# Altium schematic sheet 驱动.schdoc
size 594 x 419 mm; Symbol: Drawing-Symbol_A4; Company: 嘉立创EDA; Version: V1.0; Page Size: A4; @Project Name: FOC; @Update Date: 2026-07-20; @Create Date: 2026-07-20; Device: Drawing-Symbol_A4; @Board Name: Board1; @Page Name: P1; @Create Time: 00:30:19; @Page Count: 2; @Page No: 2; @Schematic Name: Schematic1; @Update Time: 00:30:19; @Assembly Variant: Basic; Border: 1; Title Block Position: 3; Size: A4; Width: 2338; Height: 1652; Region Start: 1; X Region Count: 6; Y Region Count: 4; Blade Width: 10
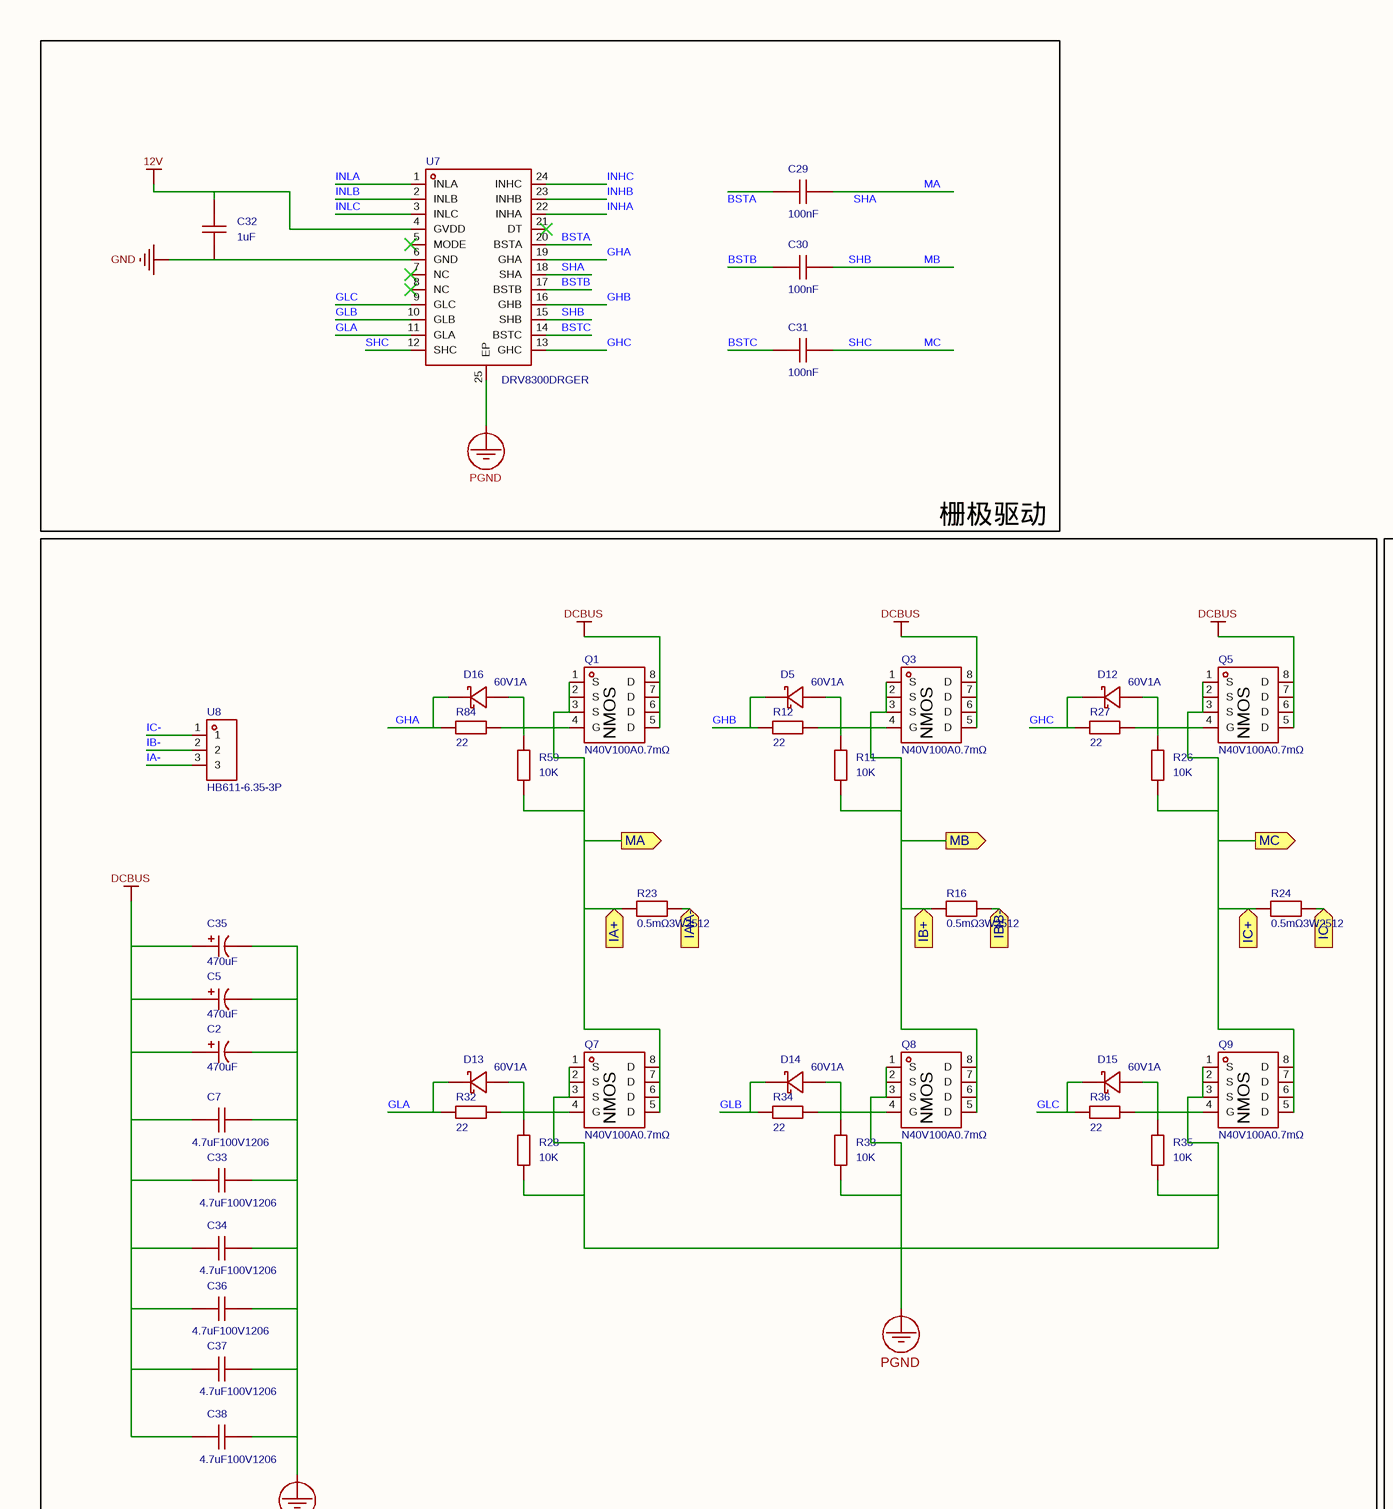
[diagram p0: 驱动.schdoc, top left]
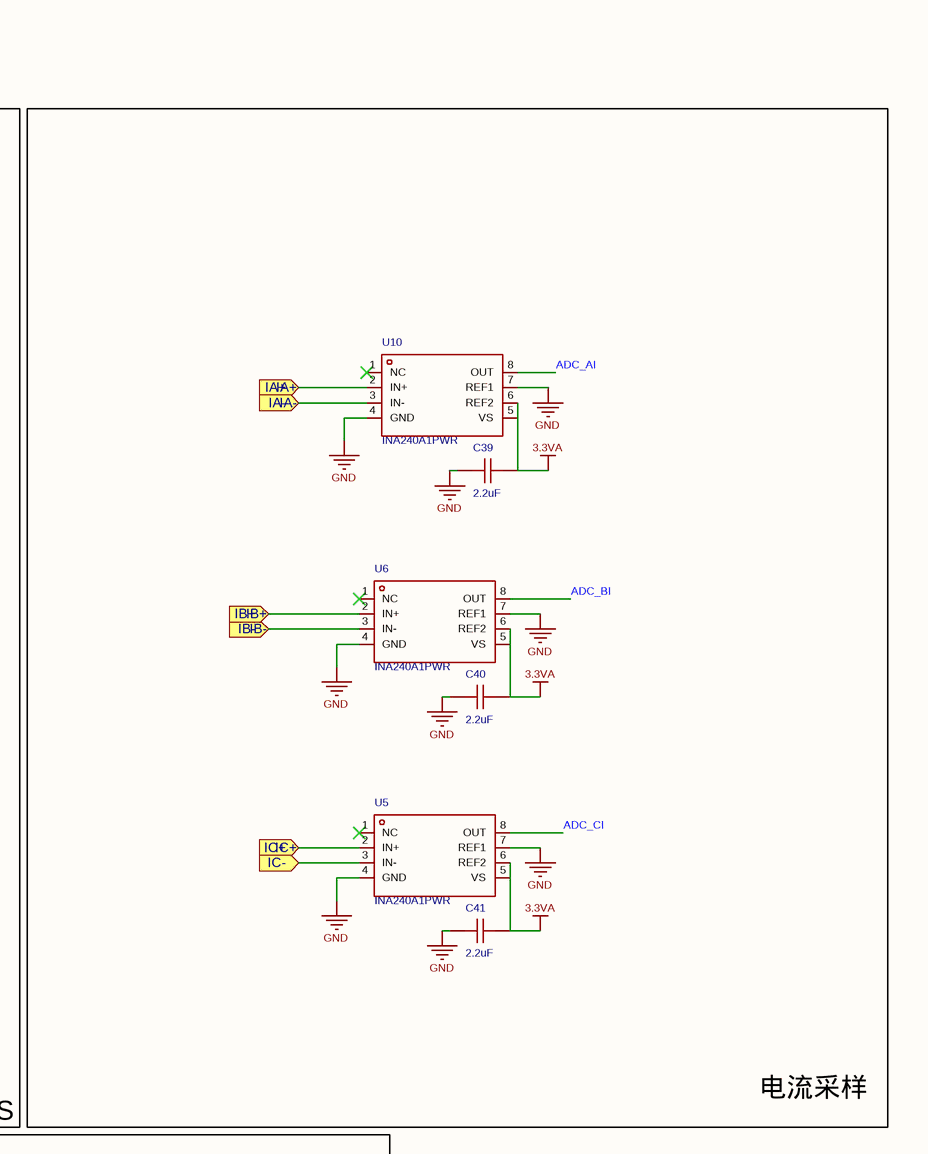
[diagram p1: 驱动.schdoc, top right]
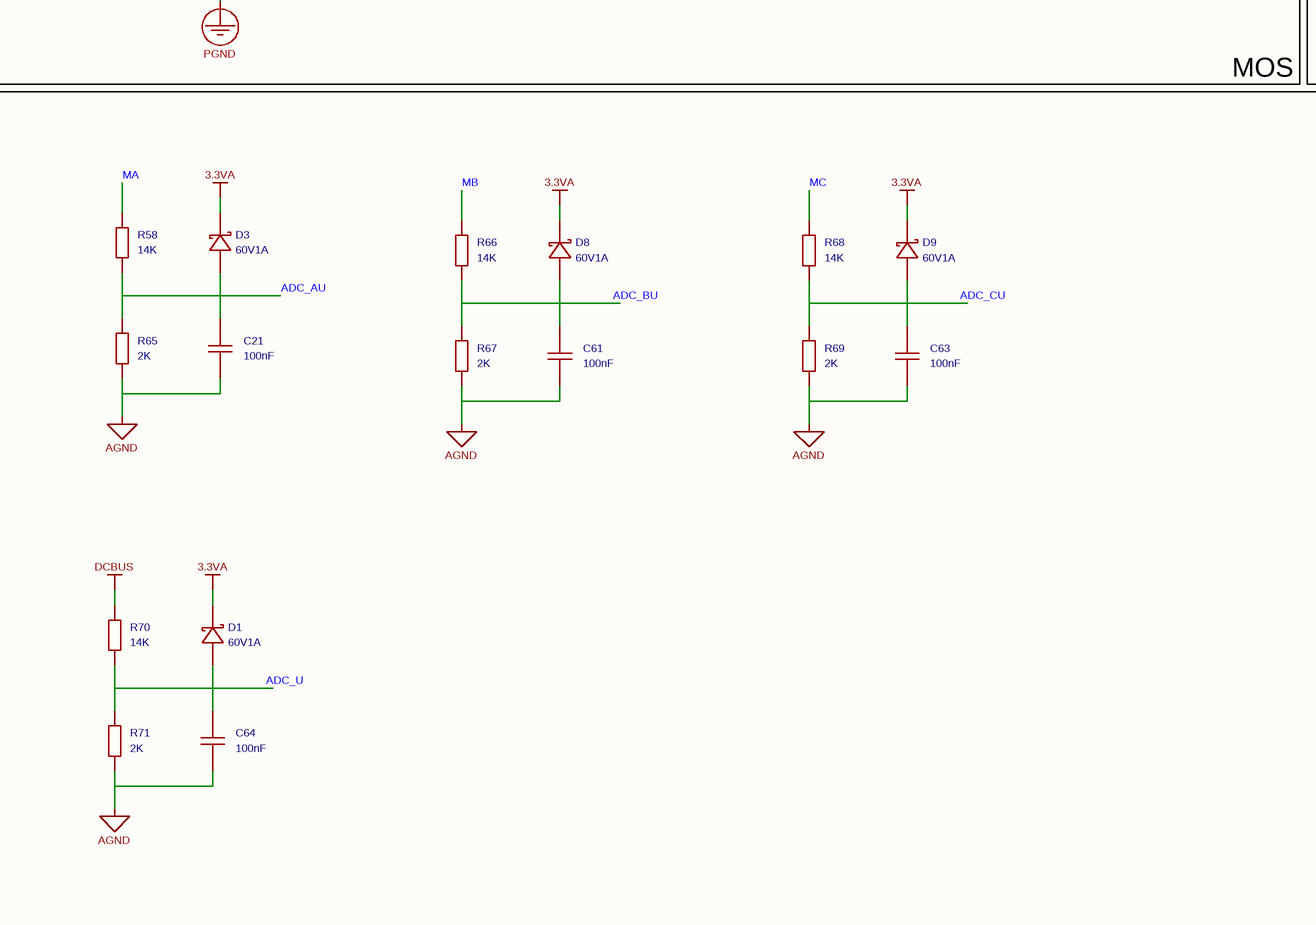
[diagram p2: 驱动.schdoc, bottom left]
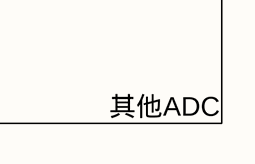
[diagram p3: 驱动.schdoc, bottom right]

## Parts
C2  470uF  [CAP-TH_BD13.0-P5.00-D0.6-FD]
C5  470uF  [CAP-TH_BD13.0-P5.00-D0.6-FD]
C7  4.7uF100V1206  [C1206]
C21  100nF  [C0603]
C29  100nF  [C0603]
C30  100nF  [C0603]
C31  100nF  [C0603]
C32  1uF  [C0603]
C33  4.7uF100V1206  [C1206]
C34  4.7uF100V1206  [C1206]
C35  470uF  [CAP-TH_BD13.0-P5.00-D0.6-FD]
C36  4.7uF100V1206  [C1206]
C37  4.7uF100V1206  [C1206]
C38  4.7uF100V1206  [C1206]
C39  2.2uF  [C0603]
C40  2.2uF  [C0603]
C41  2.2uF  [C0603]
C61  100nF  [C0603]
C63  100nF  [C0603]
C64  100nF  [C0603]
D1  60V1A  [SOD-323_L1.7-W1.3-LS2.5-FD]
D3  60V1A  [SOD-323_L1.7-W1.3-LS2.5-FD]
D5  60V1A  [SOD-323_L1.7-W1.3-LS2.5-FD]
D8  60V1A  [SOD-323_L1.7-W1.3-LS2.5-FD]
D9  60V1A  [SOD-323_L1.7-W1.3-LS2.5-FD]
D12  60V1A  [SOD-323_L1.7-W1.3-LS2.5-FD]
D13  60V1A  [SOD-323_L1.7-W1.3-LS2.5-FD]
D14  60V1A  [SOD-323_L1.7-W1.3-LS2.5-FD]
D15  60V1A  [SOD-323_L1.7-W1.3-LS2.5-FD]
D16  60V1A  [SOD-323_L1.7-W1.3-LS2.5-FD]
Q1  N40V100A0.7mΩ  [PG-TDSON-8-FL_L5.0-W6.0-P1.27-LS6.2-BL]
Q3  N40V100A0.7mΩ  [PG-TDSON-8-FL_L5.0-W6.0-P1.27-LS6.2-BL]
Q5  N40V100A0.7mΩ  [PG-TDSON-8-FL_L5.0-W6.0-P1.27-LS6.2-BL]
Q7  N40V100A0.7mΩ  [PG-TDSON-8-FL_L5.0-W6.0-P1.27-LS6.2-BL]
Q8  N40V100A0.7mΩ  [PG-TDSON-8-FL_L5.0-W6.0-P1.27-LS6.2-BL]
Q9  N40V100A0.7mΩ  [PG-TDSON-8-FL_L5.0-W6.0-P1.27-LS6.2-BL]
R11  10K  [R0603]
R12  22  [R0603]
R16  0.5mΩ3W2512  [R2512]
R23  0.5mΩ3W2512  [R2512]
R24  0.5mΩ3W2512  [R2512]
R26  10K  [R0603]
R27  22  [R0603]
R28  10K  [R0603]
R32  22  [R0603]
R33  10K  [R0603]
R34  22  [R0603]
R35  10K  [R0603]
R36  22  [R0603]
R58  14K  [R0603]
R59  10K  [R0603]
R65  2K  [R0603]
R66  14K  [R0603]
R67  2K  [R0603]
R68  14K  [R0603]
R69  2K  [R0603]
R70  14K  [R0603]
R71  2K  [R0603]
R84  22  [R0603]
U5  INA240A1PWR  [TSSOP-8_L4.4-W3.0-P0.65-LS6.4-BL]
U6  INA240A1PWR  [TSSOP-8_L4.4-W3.0-P0.65-LS6.4-BL]
U7  DRV8300DRGER  [VQFN-24_L4.0-W4.0-P0.50-TL-EP2.5]
U8  HB611-6.35-3P  [CONN-TH_HB611-6.35-3P]
U10  INA240A1PWR  [TSSOP-8_L4.4-W3.0-P0.65-LS6.4-BL]

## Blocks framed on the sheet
栅极驱动: C29-C32 U7
MOS: C2 C5 C7 C33-C38 D5 D12-D16 Q1 Q3 Q5 Q7-Q9 R11 R12 R16 R23 R24 R26-R28 R32-R36 R59 R84 U8
电流采样: C39-C41 U5 U6 U10
其他ADC: C21 C61 C63 C64 D1 D3 D8 D9 R58 R65-R71

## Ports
IA+ (in), IA- (in), IB+ (in), IB- (in), IC+ (in), IC- (in), MA (out), MB (out), MC (out)

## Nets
3.3VA: C39.2 C40.2 C41.2 D1.2(K) D3.2(K) D8.2(K) D9.2(K) U5.5(VS) U5.6(REF2) U6.5(VS) U6.6(REF2) U10.5(VS) U10.6(REF2)
12V: C32.2 U7.4(GVDD)
AGND: C21.1 C61.1 C63.1 C64.1 R65.1 R67.1 R69.1 R71.1
DCBUS: C2.1 C5.1 C7.1 C33.1 C34.1 C35.1 C36.1 C37.1 C38.1 Q1.5(D) Q1.6(D) Q1.7(D) Q1.8(D) Q3.5(D) Q3.6(D) Q3.7(D) Q3.8(D) Q5.5(D) Q5.6(D) Q5.7(D) Q5.8(D) R70.2
GND: C32.1 C39.1 C40.1 C41.1 U5.4(GND) U5.7(REF1) U6.4(GND) U6.7(REF1) U7.6(GND) U10.4(GND) U10.7(REF1)
PGND: C2.2 C5.2 C7.2 C33.2 C34.2 C35.2 C36.2 C37.2 C38.2 Q7.1(S) Q7.2(S) Q7.3(S) Q8.1(S) Q8.2(S) Q8.3(S) Q9.1(S) Q9.2(S) Q9.3(S) R28.1 R33.1 R35.1 U7.25(EP)
ADC_AI: U10.8(OUT)
ADC_AU: C21.2 D3.1(A) R58.1 R65.2
ADC_BI: U6.8(OUT)
ADC_BU: C61.2 D8.1(A) R66.1 R67.2
ADC_CI: U5.8(OUT)
ADC_CU: C63.2 D9.1(A) R68.1 R69.2
ADC_U: C64.2 D1.1(A) R70.1 R71.2
BSTA: C29.2 U7.20(BSTA)
BSTB: C30.1 U7.17(BSTB)
BSTC: C31.1 U7.14(BSTC)
GHA: D16.2(K) R84.1 U7.19(GHA)
GHB: D5.2(K) R12.1 U7.16(GHB)
GHC: D12.2(K) R27.1 U7.13(GHC)
GLA: D13.2(K) R32.1 U7.11(GLA)
GLB: D14.2(K) R34.1 U7.10(GLB)
GLC: D15.2(K) R36.1 U7.9(GLC)
IA+: Q1.1(S) Q1.2(S) Q1.3(S) Q7.5(D) Q7.6(D) Q7.7(D) Q7.8(D) R23.1 R59.1 U10.2(IN+) ; port MA, port IA+
IA-: R23.2 U8.3 U10.3(IN-) ; port IA-
IB+: Q3.1(S) Q3.2(S) Q3.3(S) Q8.5(D) Q8.6(D) Q8.7(D) Q8.8(D) R11.1 R16.1 U6.2(IN+) ; port MB, port IB+
IB-: R16.2 U6.3(IN-) U8.2 ; port IB-
IC+: Q5.1(S) Q5.2(S) Q5.3(S) Q9.5(D) Q9.6(D) Q9.7(D) Q9.8(D) R24.1 R26.1 U5.2(IN+) ; port MC, port IC+
IC-: U8.1
IC-: R24.2 U5.3(IN-) ; port IC-  [a separate net that carries the same name]
INHA: U7.22(INHA)
INHB: U7.23(INHB)
INHC: U7.24(INHC)
INLA: U7.1(INLA)
INLB: U7.2(INLB)
INLC: U7.3(INLC)
MA: C29.1 R58.2 U7.18(SHA)  [also labelled SHA]
MB: C30.2 R66.2 U7.15(SHB)  [also labelled SHB]
MC: C31.2 R68.2 U7.12(SHC)  [also labelled SHC]
NetD5_1: D5.1(A) Q3.4(G) R11.2 R12.2
NetD12_1: D12.1(A) Q5.4(G) R26.2 R27.2
NetD13_1: D13.1(A) Q7.4(G) R28.2 R32.2
NetD14_1: D14.1(A) Q8.4(G) R33.2 R34.2
NetD15_1: D15.1(A) Q9.4(G) R35.2 R36.2
NetD16_1: D16.1(A) Q1.4(G) R59.2 R84.2

Not connected (* = marked no-connect by the designer): U5 1(NC)*; U6 1(NC)*; U7 5(MODE)* 7(NC)* 8(NC)* 21(DT)*; U10 1(NC)*

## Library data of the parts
C2 C5 C35 = ERG63V470M13X21: 容值:470uF;精度:±20%;额定电压:63V;纹波电流:860mA@100kHz;等效串联电阻(ESR):100mΩ@100kHz;; Manufacturer: JIERR(捷而瑞); AddInBom: yes; ModelId: d480d9258dff471ebe4ee69eb07122f60819f05c4eef4c71ace90d822a990e87; ModelName: CAP-TH_BD13.0-P5.00-D1.2-FD; ModelTransform: 492.5187,492.025,0,0,0,0,-0.005,0,-137.795; Tolerance: ±20%; Voltage Rating: 63V; Pin Spacing: 5mm; Lifetime: 2000hrs@105℃
C7 C33 C34 C36-C38 = HHV1206R7475K101NSPJ: 容值:4.7uF;精度:±10%;额定电压:100V;温度系数:X7R;; Manufacturer: Chinocera(华瓷); AddInBom: yes; ModelId: e4be705b945545a48e666415e3682bd80819f05c4eef4c71ace90d822a990e87; ModelName: C1206_L3.2-W1.6-H1.3; ModelTransform: 125.984,62.992,0,0,0,0,0,0,0; Tolerance: ±10%; Voltage Rating: 100V; Temperature Coefficient: X7R
C21 C29-C32 C39-C41 C61 C63 C64 = CAP_0603: Symbol: Capacitance; 3D Model: ac125912035d415993ca9572d50418b10819f05c4eef4c71ace90d822a990e87; 3D Model Transform: 62.992,31.496,0,0,0,0,0,0,0; ConvertToPcb: yes; ModelName: C0603_L1.6-W0.8-H0.8
D1 D5 D12-D15 = B16WS_C7420327: 二极管配置:独立式;正向压降(Vf):700mV@1A;直流反向耐压(Vr):60V;整流电流:1A;; Manufacturer: R+O(宏嘉诚); 3D Model: 0f2f330c645944df9245ac3c3fec34560819f05c4eef4c71ace90d822a990e87; 3D Model Transform: 98.425,49.2125,0,180,0,0,0,0,0; Diode Configuration: 独立式; Voltage - DC Reverse(Vr): 60V; Current - Rectified: 1A; Reverse Leakage Current (Ir): 100uA@60V; Operating Junction Temperature Range: -55℃~+150℃; Non-Repetitive Peak Forward Surge Current: 10A; AddInBom: yes
D3 D8 D9 D16 = B16WS_C7420327: 二极管配置:独立式;正向压降(Vf):700mV@1A;直流反向耐压(Vr):60V;整流电流:1A;; Manufacturer: R+O(宏嘉诚); AddInBom: yes; ModelId: 0f2f330c645944df9245ac3c3fec34560819f05c4eef4c71ace90d822a990e87; ModelTransform: 98.425,49.2125,0,180,0,0,0,0,0; Diode Configuration: 独立式; Voltage - DC Reverse(Vr): 60V; Current - Rectified: 1A; Reverse Leakage Current (Ir): 100uA@60V; Operating Junction Temperature Range: -55℃~+150℃; Non-Repetitive Peak Forward Surge Current: 10A
Q1 = BSC007N04LS6: 数量:1个N沟道;漏源电压(Vdss):40V;连续漏极电流(Id):100A;导通电阻(RDS(on)):0.7mΩ@10V;耗散功率(Pd):188W;阈值电压(Vgs(th)):2.3V;; Manufacturer: Infineon(英飞凌); AddInBom: yes; ModelId: a72bae87227d40a2b79dea17b4cf16f50819f05c4eef4c71ace90d822a990e87; ModelName: PG-TDSON-8-FL_L5.0-W6.0-H1.0-P1.27-LS6.2-BL; ModelTransform: 212.9917,242.1255,0,0,0,0,-0.002,0.002,0; Number: 1个N沟道; Drain to Source Voltage: 40V; Current - Continuous Drain(Id): 100A; Pd - Power Dissipation: 188W; Gate Threshold Voltage (Vgs(th)): 2.3V; Gate Charge(Qg): 94nC; Input Capacitance(Ciss): 8.4nF; Reverse Transfer Capacitance (Crss@Vds): 89pF; Type: N沟道; Output Capacitance(Coss): 2.1nF; Vgs: ±20V
Q3 Q5 Q7-Q9 = BSC007N04LS6: 数量:1个N沟道;漏源电压(Vdss):40V;连续漏极电流(Id):100A;导通电阻(RDS(on)):0.7mΩ@10V;耗散功率(Pd):188W;阈值电压(Vgs(th)):2.3V;; Manufacturer: Infineon(英飞凌); 3D Model: a72bae87227d40a2b79dea17b4cf16f50819f05c4eef4c71ace90d822a990e87; 3D Model Transform: 212.9917,242.1255,0,0,0,0,-0.002,0.002,0; Number: 1个N沟道; Drain to Source Voltage: 40V; Current - Continuous Drain(Id): 100A; Pd - Power Dissipation: 188W; Gate Threshold Voltage (Vgs(th)): 2.3V; Gate Charge(Qg): 94nC; Input Capacitance(Ciss): 8.4nF; Reverse Transfer Capacitance (Crss@Vds): 89pF; Type: N沟道; Output Capacitance(Coss): 2.1nF; Vgs: ±20V; AddInBom: yes; ModelName: PG-TDSON-8-FL_L5.0-W6.0-H1.0-P1.27-LS6.2-BL
R11 R12 R26-R28 R32-R36 R58 R59 R65-R71 R84 = Res_0603: Symbol: 电阻; 3D Model: fc143cca1e79419f9cd78b61e9279f080819f05c4eef4c71ace90d822a990e87; 3D Model Transform: 31.8897,63.7794,0,90,0,0,0,0,0; ConvertToPcb: yes
R16 R23 R24 = HoYLR2512E-3W-0.5mR-1%: 电阻类型:采样电阻;阻值:0.5mΩ;精度:±1%;功率:3W;安装方式:贴片;; Manufacturer: Milliohm(毫欧); AddInBom: yes; ModelId: 954b67263d9e4f3582d8de3f8c8464210819f05c4eef4c71ace90d822a990e87; ModelName: R2512_L6.3-W3.2-H0.6; ModelTransform: 248.031,125.984,0,0,0,0,-0.0005,0,0; Tolerance: ±1%; Power(Watts): 3W
U5 U6 = INA240A1PWR: 放大器数:1;共模电压:-4V~80V;增益:20V/V;带宽(-3db):400kHz;; Manufacturer: TI(德州仪器); 3D Model: 85577802f9634e7e85ffa2fd25a37b6f0819f05c4eef4c71ace90d822a990e87; 3D Model Transform: 118.11,251.968,0,0,0,0,0,0,0; Number of Channels: 1; Gain: 20V/V; Bandwidth: 400kHz; Ib - Input Bias Current: 90uA; Vos - Input Offset Voltage: 5uV; Differential Voltage: ±80V; Single Supply: 2.7V~5.5V; Quiescent Current: 1.8mA; Input Offset Voltage Drift(Vos TC): 250nV/℃; Slew Rate: 2V/us; Common Mode Rejection Ratio (CMRR): 132dB; Noise density(eN): 40nV/√Hz@1kHz; AddInBom: yes; ModelName: TSSOP-8_L4.4-W3.0-P0.65-LS6.4-BL-2
U7 = DRV8300DRGER_C3655801: DRV8300 具有自举二极管的最大 100V 简单三相栅极驱动器; Manufacturer: TI(德州仪器); AddInBom: yes; ModelId: 45d01521fd6b4217a75fbd67391c0e910819f05c4eef4c71ace90d822a990e87; ModelTransform: 158.267,158.267,0,0,0,0,0,0,0
U8 = HB611-6.35-3P: 隔板类型:三面;间距:6.35mm;结构:1x3P;安装方式:直插;引脚位置:边脚;排数:1;每排PIN数:3;额定电流:24A;额定电压:450V;线规 - AWG:12~22;线规 - 平方毫米:2.5;工作温度:-40℃~+105℃;颜色:黑色;; Manufacturer: KEFA(科发); 3D Model: c87b4a32e78a434c8415c321f1d661b10819f05c4eef4c71ace90d822a990e87; 3D Model Transform: 797.2425,562.991,0,0,0,0,0,-104.331,-165.354; Barrier Type: 三面; Pitch: 6.35mm; Number of Positions or Pins: 1x3P; Pin Location: 边脚; Number of PINs Per Row: 3; Current Rating: 24A; Voltage Rating (Max): 450V; Wire Gauge - AWG: 12~22; Wire Gauge - mm2: 2.5; AddInBom: yes
U10 = INA240A1PWR: 放大器数:1;共模电压:-4V~80V;增益:20V/V;带宽(-3db):400kHz;; Manufacturer: TI(德州仪器); AddInBom: yes; ModelId: 85577802f9634e7e85ffa2fd25a37b6f0819f05c4eef4c71ace90d822a990e87; ModelName: TSSOP-8_L4.4-W3.0-P0.65-LS6.4-BL-2; ModelTransform: 118.11,251.968,0,0,0,0,0,0,0; Number of Channels: 1; Gain: 20V/V; Bandwidth: 400kHz; Ib - Input Bias Current: 90uA; Vos - Input Offset Voltage: 5uV; Differential Voltage: ±80V; Single Supply: 2.7V~5.5V; Quiescent Current: 1.8mA; Input Offset Voltage Drift(Vos TC): 250nV/℃; Slew Rate: 2V/us; Common Mode Rejection Ratio (CMRR): 132dB; Noise density(eN): 40nV/√Hz@1kHz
